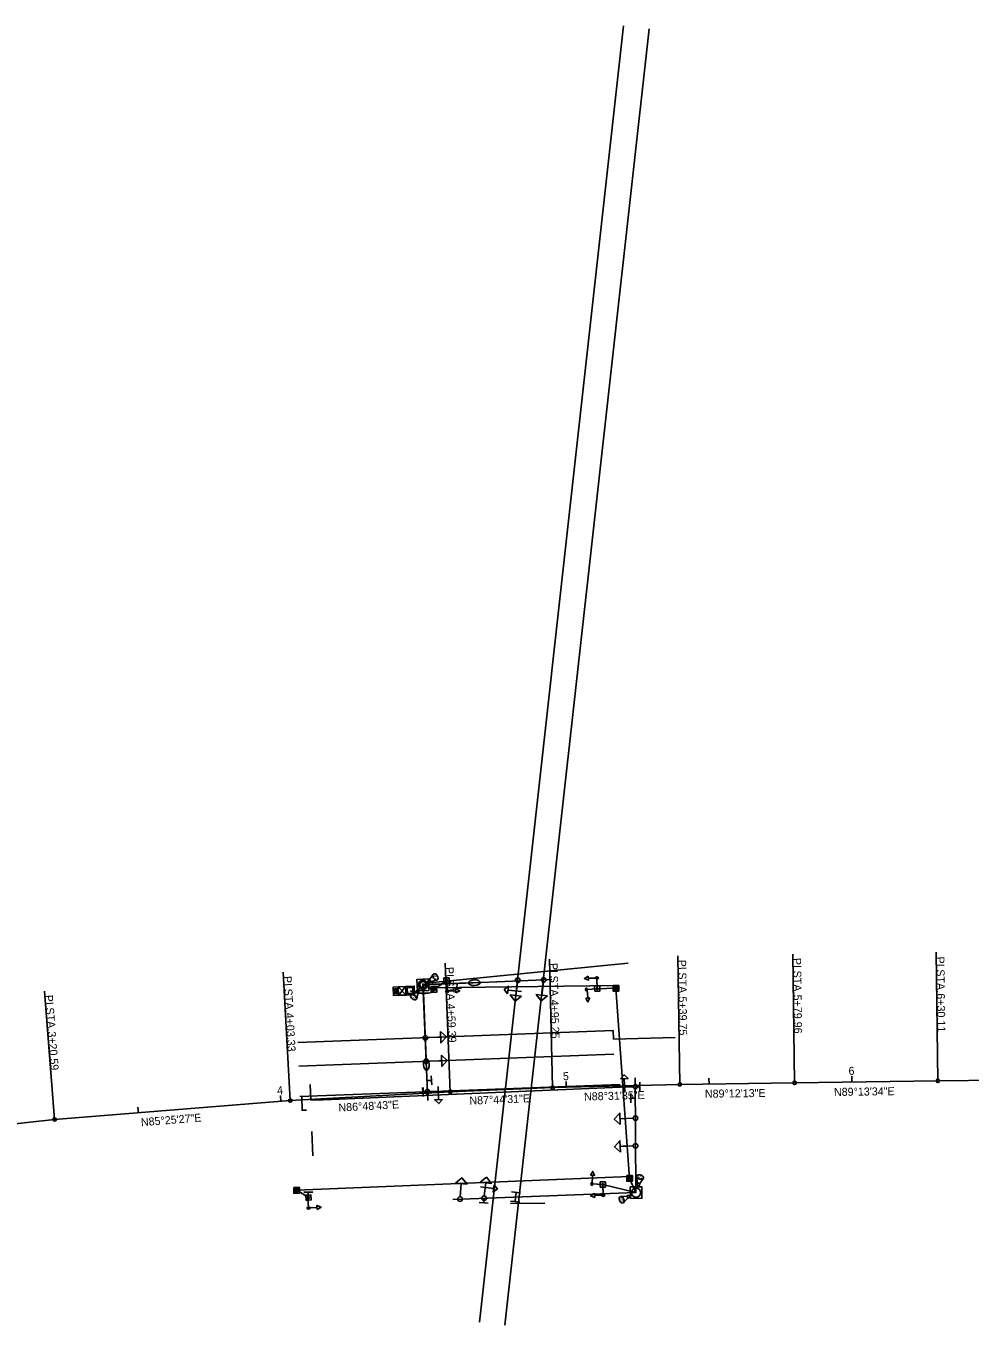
# Model space of a CAD drawing. Extents: x 1369241 to 1370511, y 405823 to 406278.
# Drawn here: x 1369555.1 to 1369885.4, y 405822.9 to 406277.6 of the extents above; entities that cross this region are included whole.
import ezdxf

# ---------------------------------------------------------------- set-up
doc = ezdxf.new("R2010")
doc.units = 0
for name, color, linetype in [('_CIVIL_CONSTRUCTION', 7, 'Continuous'), ('CM_Corridor_Conceptual', 7, 'Continuous'), ('CM_Corridor_Range_Conceptual', 7, 'Continuous'), ('DT_P_Tie', 7, 'Continuous'), ('GE_P_Alignment', 7, 'Continuous'), ('MD_P_ACB_B', 7, 'Continuous'), ('MD_P_ACIC_B', 7, 'Continuous'), ('MD_P_ACSC_T', 7, 'Continuous'), ('MD_P_CSS_B', 7, 'Continuous'), ('MD_P_CURB_BACK_BOT', 7, 'Continuous'), ('MD_P_CURB_BACK_TOP', 7, 'Continuous'), ('MD_P_CURB_FACE_TOP', 7, 'Continuous'), ('PM_P_Crosswalk', 7, 'Continuous'), ('SC_Scratch1', 7, 'Continuous')]:
    doc.layers.add(name, color=color, linetype=linetype)

msp = doc.modelspace()

# ---------------------------------------------------------------- linework, layer by layer
at = {"layer": '_CIVIL_CONSTRUCTION'}
for p, q in [((1369685.39, 405938.97), (1369684.07, 405940.53)), ((1369684.14, 405938.91), (1369685.31, 405940.59)), ((1369688.08, 405938.41), (1369685.28, 405941.28)), ((1369685.42, 405938.28), (1369687.94, 405941.4))]:
    msp.add_line(p, q, dxfattribs=at)
for points in [[(1369691.08, 405938.55), (1369690.94, 405941.54), (1369683.57, 405941.2), (1369683.71, 405938.2)], [(1369685.39, 405938.97), (1369684.14, 405938.91), (1369684.07, 405940.53), (1369685.31, 405940.59)], [(1369688.08, 405938.41), (1369685.42, 405938.28), (1369685.28, 405941.28), (1369687.94, 405941.4)], [(1369691.08, 405938.55), (1369690.94, 405941.54), (1369687.94, 405941.4), (1369688.08, 405938.41)], [(1369690.56, 405939.02), (1369690.46, 405941.02), (1369688.47, 405940.93), (1369688.56, 405938.93)]]:
    msp.add_lwpolyline(points, close=True, dxfattribs=at)
at = {"layer": 'CM_Corridor_Conceptual'}
for p, q in [((1369702.28, 405944.43), (1369702.28, 405944.43)), ((1369728.43, 405939.62), (1369723.76, 405940.16)), ((1369727.07, 405942.78), (1369726.53, 405938.22)), ((1369736.14, 405942.93), (1369735.61, 405938.37)), ((1369756.1, 405940.72), (1369756.1, 405940.72)), ((1369755.03, 405939.65), (1369755.03, 405939.65)), ((1369695.61, 405923.5), (1369700.21, 405923.67)), ((1369695.93, 405915.24), (1369700.52, 405915.41)), ((1369764.6, 405904.48), (1369764.42, 405909.18)), ((1369696.37, 405904.61), (1369700.97, 405904.8)), ((1369699.28, 405906.45), (1369699.48, 405901.75)), ((1369767.52, 405906.31), (1369762.92, 405906.13)), ((1369767.56, 405895.29), (1369762.97, 405895.1)), ((1369767.6, 405885.59), (1369763.01, 405885.4)), ((1369707.05, 405867.81), (1369707.41, 405872.39)), ((1369715.47, 405868.11), (1369715.98, 405872.68)), ((1369756.91, 405873.05), (1369756.91, 405873.05)), ((1369757.88, 405872.04), (1369757.88, 405872.04)), ((1369653.67, 405868.6), (1369653.67, 405868.6)), ((1369714.1, 405871.26), (1369718.77, 405870.74))]:
    msp.add_line(p, q, dxfattribs=at)
for points in [[(1369751.87, 405944.96), (1369751.91, 405943.56), (1369750.49, 405944.22)], [(1369705.49, 405939.15), (1369705.43, 405940.54), (1369706.86, 405939.9)], [(1369723.61, 405938.86), (1369722.44, 405940.34), (1369723.92, 405941.51)], [(1369728.53, 405937.99), (1369726.31, 405936.24), (1369724.55, 405938.46)], [(1369737.59, 405938.14), (1369735.37, 405936.38), (1369733.62, 405938.6)], [(1369750.94, 405937.32), (1369752.34, 405937.43), (1369751.74, 405935.98)], [(1369700.13, 405925.67), (1369702.21, 405923.75), (1369700.28, 405921.67)], [(1369700.45, 405917.41), (1369702.52, 405915.49), (1369700.6, 405913.41)], [(1369763.1, 405909.12), (1369764.38, 405910.5), (1369765.76, 405909.22)], [(1369700.8, 405901.81), (1369699.53, 405900.43), (1369698.14, 405901.7)], [(1369763.05, 405893.1), (1369760.97, 405895.02), (1369762.89, 405897.1)], [(1369763.1, 405883.41), (1369761.01, 405885.32), (1369762.93, 405887.4)], [(1369752.66, 405875.34), (1369754.06, 405875.26), (1369753.44, 405876.7)], [(1369705.42, 405872.55), (1369707.57, 405874.38), (1369709.41, 405872.23)], [(1369713.99, 405872.89), (1369716.2, 405874.66), (1369717.96, 405872.44)], [(1369718.91, 405872.04), (1369720.08, 405870.57), (1369718.61, 405869.39)], [(1369754.1, 405867.54), (1369754.05, 405868.94), (1369752.68, 405868.19)], [(1369656.97, 405863.38), (1369656.89, 405864.78), (1369658.33, 405864.16)]]:
    msp.add_lwpolyline(points, close=True, dxfattribs=at)
for points in [[(1369754.99, 405940.85), (1369754.89, 405944.35), (1369751.89, 405944.26)], [(1369702.33, 405943.23), (1369702.46, 405939.73), (1369705.46, 405939.85)], [(1369754.9, 405940.63), (1369751.41, 405940.37), (1369751.64, 405937.38)], [(1369756.68, 405872.1), (1369753.19, 405872.31), (1369753.36, 405875.3)], [(1369756.95, 405871.85), (1369757.08, 405868.35), (1369754.08, 405868.24)], [(1369653.74, 405867.4), (1369653.94, 405863.91), (1369656.93, 405864.08)]]:
    msp.add_lwpolyline(points, dxfattribs=at)
for centre in [(1369727.16, 405943.58), (1369736.23, 405943.73), (1369694.81, 405923.47), (1369695.13, 405915.21), (1369695.57, 405904.58), (1369768.32, 405906.34), (1369768.36, 405895.33), (1369768.4, 405885.63), (1369706.99, 405867.01), (1369715.38, 405867.31)]:
    msp.add_circle(centre, 0.8, dxfattribs=at)
at = {"layer": 'CM_Corridor_Range_Conceptual'}
for p, q in [((1369694.1, 405939.15), (1369694.05, 405940.75)), ((1369707.49, 405940.72), (1369704.3, 405940.98)), ((1369705.89, 405940.85), (1369706.02, 405942.44)), ((1369705.89, 405940.85), (1369705.89, 405940.85)), ((1369695.7, 405939.2), (1369692.5, 405939.1)), ((1369694.1, 405939.15), (1369694.1, 405939.15)), ((1369696.98, 405908.53), (1369695.38, 405908.46)), ((1369696.92, 405910.13), (1369697.05, 405906.93)), ((1369696.98, 405908.53), (1369696.98, 405908.53)), ((1369694.06, 405902.86), (1369693.81, 405906.05)), ((1369693.94, 405904.45), (1369695.53, 405904.58)), ((1369693.94, 405904.45), (1369693.94, 405904.45)), ((1369766.74, 405900.73), (1369766.73, 405903.93)), ((1369769.92, 405906.34), (1369768.32, 405906.34)), ((1369769.91, 405907.94), (1369769.92, 405904.74)), ((1369769.92, 405906.34), (1369769.92, 405906.34)), ((1369766.73, 405902.33), (1369768.33, 405902.34)), ((1369766.73, 405902.33), (1369766.73, 405902.33)), ((1369652.26, 405869.4), (1369655.46, 405869.47)), ((1369653.86, 405869.44), (1369653.9, 405867.84)), ((1369653.86, 405869.44), (1369653.86, 405869.44)), ((1369715.25, 405865.73), (1369715.38, 405867.32)), ((1369724.98, 405869.48), (1369728.16, 405869.13)), ((1369726.26, 405866.13), (1369726.39, 405867.72)), ((1369726.57, 405869.3), (1369726.39, 405867.71)), ((1369726.57, 405869.3), (1369726.57, 405869.3)), ((1369716.84, 405865.6), (1369713.65, 405865.86)), ((1369715.25, 405865.73), (1369715.25, 405865.73)), ((1369727.86, 405866), (1369724.67, 405866.26)), ((1369726.26, 405866.13), (1369726.26, 405866.13))]:
    msp.add_line(p, q, dxfattribs=at)
at = {"layer": 'DT_P_Tie'}
for p, q in [((1369696.3, 405943.8), (1369697.54, 405945.64)), ((1369697.54, 405945.64), (1369696.3, 405943.8)), ((1369693.03, 405941), (1369692.43, 405940.13)), ((1369695.02, 405942.47), (1369695.89, 405943.07)), ((1369696.3, 405943.8), (1369696.72, 405943.18)), ((1369696.72, 405943.18), (1369698.89, 405943.65)), ((1369696.72, 405943.18), (1369698.89, 405943.65)), ((1369703.02, 405939.87), (1369701.9, 405939.82)), ((1369702.32, 405943.44), (1369702.46, 405939.85)), ((1369751.45, 405939.81), (1369751.37, 405940.93)), ((1369755, 405940.64), (1369751.41, 405940.37)), ((1369754.33, 405944.22), (1369755.45, 405944.25)), ((1369755, 405940.64), (1369754.89, 405944.24)), ((1369691.7, 405939.72), (1369689.85, 405938.5)), ((1369691.7, 405939.72), (1369689.85, 405938.5)), ((1369692.32, 405939.3), (1369691.7, 405939.72)), ((1369692.32, 405939.3), (1369691.83, 405937.14)), ((1369691.83, 405937.14), (1369692.32, 405939.3)), ((1369753.38, 405872.86), (1369753.32, 405871.74)), ((1369756.94, 405872.09), (1369753.35, 405872.3)), ((1369756.94, 405872.09), (1369757.07, 405868.49)), ((1369769.13, 405872.63), (1369768.78, 405874.82)), ((1369768.78, 405874.82), (1369769.13, 405872.63)), ((1369769.09, 405870.78), (1369769.33, 405871.81)), ((1369769.13, 405872.63), (1369769.86, 405872.46)), ((1369769.86, 405872.46), (1369771.12, 405874.28)), ((1369769.86, 405872.46), (1369771.12, 405874.28)), ((1369653.72, 405867.66), (1369653.93, 405864.06)), ((1369756.51, 405868.47), (1369757.63, 405868.51)), ((1369765.39, 405868.05), (1369763.18, 405867.95)), ((1369765.39, 405868.05), (1369763.18, 405867.95)), ((1369765.71, 405867.37), (1369764.18, 405865.77)), ((1369764.18, 405865.77), (1369765.71, 405867.37)), ((1369765.71, 405867.37), (1369765.39, 405868.05)), ((1369767.2, 405868.46), (1369766.23, 405868.02)), ((1369654.49, 405864.1), (1369653.37, 405864.03))]:
    msp.add_line(p, q, dxfattribs=at)
for points in [[(1369692.74, 405939.92), (1369692.12, 405940.34), (1369691.7, 405939.72), (1369692.32, 405939.3)], [(1369695.68, 405943.38), (1369696.1, 405942.76), (1369696.72, 405943.18), (1369696.3, 405943.8)], [(1369768.96, 405871.9), (1369769.69, 405871.73), (1369769.86, 405872.46), (1369769.13, 405872.63)], [(1369766.39, 405867.68), (1369766.08, 405868.37), (1369765.39, 405868.05), (1369765.71, 405867.37)]]:
    msp.add_lwpolyline(points, close=True, dxfattribs=at)
for points in [[(1369692.74, 405939.92), (1369692.12, 405940.34), (1369691.7, 405939.72), (1369692.32, 405939.3), (1369692.74, 405939.92)], [(1369695.68, 405943.38), (1369696.1, 405942.76), (1369696.72, 405943.18), (1369696.3, 405943.8), (1369695.68, 405943.38)], [(1369768.96, 405871.9), (1369769.69, 405871.73), (1369769.86, 405872.46), (1369769.13, 405872.63), (1369768.96, 405871.9)], [(1369766.39, 405867.68), (1369766.08, 405868.37), (1369765.39, 405868.05), (1369765.71, 405867.37), (1369766.39, 405867.68)]]:
    msp.add_lwpolyline(points, dxfattribs=at)
for centre, start, end in [((1369754.89, 405944.24), 1.7331, 181.7327), ((1369702.46, 405939.85), 182.1814, 2.181), ((1369751.41, 405940.37), 94.3061, 274.3057), ((1369753.35, 405872.3), 86.695, 266.6946), ((1369757.07, 405868.49), 182.0638, 2.0634), ((1369653.93, 405864.06), 183.273, 3.2727)]:
    msp.add_arc(centre, 0.56, start, end, dxfattribs=at)
for centre, major_axis in [((1369698.37, 405944.75), (0.7, -1.02)), ((1369690.73, 405937.66), (-1.02, 0.7)), ((1369769.99, 405874.73), (1.21, -0.28)), ((1369763.51, 405866.78), (-0.51, 1.13))]:
    msp.add_ellipse(centre, major_axis=major_axis, ratio=0.621318, dxfattribs=at)
for centre, major_axis in [((1369698.37, 405944.75), (0.7, -1.02)), ((1369690.73, 405937.66), (-1.02, 0.7)), ((1369769.99, 405874.73), (1.21, -0.28)), ((1369763.51, 405866.78), (-0.51, 1.13))]:
    msp.add_ellipse(centre, major_axis=major_axis, ratio=0.621318, start_param=3.386213, end_param=6.038231, dxfattribs=at)
at = {"layer": 'GE_P_Alignment'}
for points in [[(1369701.41, 405942.6), (1369703.21, 405942.65), (1369703.15, 405944.45), (1369701.35, 405944.4)], [(1369692.09, 405939.85), (1369696.09, 405940.05), (1369695.89, 405944.04), (1369691.9, 405943.85)], [(1369754.13, 405939.71), (1369755.93, 405939.79), (1369755.85, 405941.59), (1369754.05, 405941.5)], [(1369756.04, 405871.19), (1369757.84, 405871.19), (1369757.84, 405872.99), (1369756.04, 405872.99)], [(1369653.12, 405866.56), (1369654.91, 405866.73), (1369654.74, 405868.52), (1369652.95, 405868.35)], [(1369766.62, 405867.23), (1369770.62, 405867.3), (1369770.55, 405871.29), (1369766.55, 405871.23)]]:
    msp.add_lwpolyline(points, close=True, dxfattribs=at)
for centre, radius in [((1369702.28, 405943.52), 0.3), ((1369754.99, 405940.65), 0.3), ((1369756.94, 405872.09), 0.3), ((1369653.93, 405867.54), 0.3), ((1369768.59, 405869.26), 1.6)]:
    msp.add_circle(centre, radius, dxfattribs=at)
msp.add_ellipse((1369693.99, 405941.95), major_axis=(1.6, 0.08), ratio=0.999752, dxfattribs=at)
at = {"layer": 'MD_P_ACB_B'}
for p, q in [((1369697.81, 405940.4), (1369697.81, 405940.4)), ((1369761.51, 405940.79), (1369761.51, 405940.79)), ((1369766.29, 405874.24), (1369766.29, 405874.24)), ((1369649.75, 405870.07), (1369649.75, 405870.07))]:
    msp.add_line(p, q, dxfattribs=at)
for points in [[(1369696.76, 405941.34), (1369698.75, 405941.46), (1369698.87, 405939.46), (1369696.87, 405939.34)], [(1369760.51, 405941.79), (1369762.51, 405941.79), (1369762.51, 405939.79), (1369760.51, 405939.79)], [(1369765.29, 405875.24), (1369767.29, 405875.24), (1369767.29, 405873.24), (1369765.29, 405873.24)], [(1369648.75, 405871.07), (1369650.75, 405871.07), (1369650.75, 405869.07), (1369648.75, 405869.07)]]:
    msp.add_lwpolyline(points, close=True, dxfattribs=at)
for points in [[(1369696.87, 405941.01), (1369697.7, 405941.06)], [(1369697.29, 405941.03), (1369697.37, 405939.7)], [(1369697.93, 405939.74), (1369697.85, 405941.07), (1369698.35, 405941.1), (1369698.4, 405941.09), (1369698.48, 405941.07), (1369698.51, 405941.05), (1369698.54, 405941.04), (1369698.59, 405940.99), (1369698.62, 405940.94), (1369698.65, 405940.85), (1369698.66, 405940.73), (1369698.65, 405940.68), (1369698.63, 405940.62), (1369698.59, 405940.54), (1369698.55, 405940.51), (1369698.52, 405940.49), (1369698.5, 405940.48), (1369698.47, 405940.46), (1369698.38, 405940.45), (1369697.89, 405940.42)], [(1369698.38, 405940.45), (1369698.71, 405939.78)], [(1369760.6, 405941.45), (1369761.43, 405941.45)], [(1369761.02, 405941.45), (1369761.02, 405940.12)], [(1369761.58, 405940.12), (1369761.58, 405941.45), (1369762.09, 405941.45), (1369762.14, 405941.44), (1369762.21, 405941.42), (1369762.24, 405941.4), (1369762.28, 405941.38), (1369762.32, 405941.33), (1369762.35, 405941.27), (1369762.37, 405941.19), (1369762.37, 405941.06), (1369762.36, 405941.02), (1369762.34, 405940.96), (1369762.3, 405940.89), (1369762.25, 405940.85), (1369762.22, 405940.83), (1369762.2, 405940.82), (1369762.17, 405940.81), (1369762.08, 405940.8), (1369761.58, 405940.8)], [(1369762.08, 405940.8), (1369762.37, 405940.12)], [(1369765.38, 405874.9), (1369766.21, 405874.9)], [(1369765.8, 405874.9), (1369765.8, 405873.57)], [(1369766.36, 405873.57), (1369766.36, 405874.9), (1369766.87, 405874.9), (1369766.92, 405874.89), (1369766.99, 405874.87), (1369767.02, 405874.85), (1369767.05, 405874.83), (1369767.1, 405874.78), (1369767.13, 405874.72), (1369767.15, 405874.64), (1369767.15, 405874.51), (1369767.14, 405874.47), (1369767.12, 405874.41), (1369767.08, 405874.34), (1369767.03, 405874.3), (1369767, 405874.28), (1369766.98, 405874.27), (1369766.95, 405874.26), (1369766.85, 405874.25), (1369766.36, 405874.25)], [(1369766.85, 405874.25), (1369767.15, 405873.57)], [(1369648.85, 405870.74), (1369649.68, 405870.74)], [(1369649.27, 405870.74), (1369649.27, 405869.41)], [(1369649.83, 405869.41), (1369649.83, 405870.74), (1369650.33, 405870.74), (1369650.39, 405870.73), (1369650.46, 405870.71), (1369650.49, 405870.69), (1369650.52, 405870.67), (1369650.56, 405870.61), (1369650.6, 405870.56), (1369650.62, 405870.48), (1369650.62, 405870.35), (1369650.61, 405870.31), (1369650.59, 405870.25), (1369650.54, 405870.17), (1369650.5, 405870.14), (1369650.47, 405870.12), (1369650.45, 405870.11), (1369650.42, 405870.1), (1369650.32, 405870.09), (1369649.83, 405870.09)], [(1369650.32, 405870.09), (1369650.62, 405869.41)]]:
    msp.add_lwpolyline(points, dxfattribs=at)
at = {"layer": 'MD_P_ACIC_B'}
for p, q in [((1369693.99, 405942.47), (1369695.7, 405901.5)), ((1369697.81, 405940.4), (1369694.03, 405942.06)), ((1369761.54, 405941.71), (1369697.68, 405940.95)), ((1369702.32, 405943.48), (1369697.81, 405940.4)), ((1369761.51, 405940.79), (1369755, 405940.64)), ((1369761.51, 405940.79), (1369766.29, 405874.24)), ((1369766.24, 405874.9), (1369649.83, 405870.08)), ((1369768.52, 405869.25), (1369756.94, 405872.09)), ((1369766.29, 405874.24), (1369768.52, 405869.25)), ((1369649.83, 405870.08), (1369653.93, 405867.54))]:
    msp.add_line(p, q, dxfattribs=at)
msp.add_arc((1369693.98, 405949.72), 10.77, 245.4119, 291.0837, dxfattribs=at)
at = {"layer": 'MD_P_ACSC_T'}
for p, q in [((1369694.01, 405942.06), (1369709.99, 405942.66)), ((1369694.01, 405942.07), (1369695.09, 405916.09))]:
    msp.add_line(p, q, dxfattribs=at)
for centre in [(1369694.01, 405942.07), (1369694.01, 405942.06)]:
    msp.add_circle(centre, 1.1, dxfattribs=at)
for centre, major_axis in [((1369711.99, 405942.73), (2, 0.08)), ((1369695.17, 405914.09), (0.08, -2))]:
    msp.add_ellipse(centre, major_axis=major_axis, ratio=0.5, dxfattribs=at)
at = {"layer": 'MD_P_CSS_B'}
for p, q in [((1369744.13, 405906.12), (1369744.08, 405908.12)), ((1369794.12, 405907.28), (1369794.09, 405909.28)), ((1369824.07, 405907.7), (1369874.22, 405908.38)), ((1369844.11, 405907.97), (1369844.09, 405909.97)), ((1369874.22, 405908.38), (1369958.19, 405909.51)), ((1369647.58, 405901.47), (1369703.55, 405904.59)), ((1369694.18, 405904.06), (1369694.06, 405906.06)), ((1369703.55, 405904.59), (1369739.38, 405906)), ((1369739.38, 405906), (1369783.87, 405907.14)), ((1369783.87, 405907.14), (1369824.07, 405907.7)), ((1369565.1, 405894.87), (1369647.58, 405901.47)), ((1369594.42, 405897.21), (1369594.26, 405899.21)), ((1369644.26, 405901.2), (1369644.1, 405903.2)), ((1369493.58, 405887.19), (1369565.1, 405894.87))]:
    msp.add_line(p, q, dxfattribs=at)
at = {"layer": 'MD_P_CURB_BACK_BOT'}
for p, q in [((1369713.74, 405823.92), (1369764.23, 406277.56)), ((1369722.69, 405822.93), (1369773.18, 406276.56)), ((1369760.57, 405925.96), (1369650.23, 405921.77)), ((1369760.66, 405922.96), (1369760.57, 405925.96)), ((1369782.24, 405923.55), (1369760.66, 405922.94)), ((1369760.81, 405917.7), (1369650.54, 405913.51)), ((1369762.99, 405907.16), (1369650.95, 405902.9)), ((1369656.47, 405901.66), (1369765.79, 405906.23)), ((1369763.96, 405885.47), (1369765.07, 405885.47)), ((1369655.32, 405885.08), (1369655.41, 405882.08)), ((1369736.59, 405865.56), (1369724.59, 405865.44))]:
    msp.add_line(p, q, dxfattribs=at)
at = {"layer": 'MD_P_CURB_BACK_TOP'}
for p, q in [((1369651.58, 405902.91), (1369651.77, 405897.91)), ((1369651.81, 405898.11), (1369653.23, 405898.17))]:
    msp.add_line(p, q, dxfattribs=at)
at = {"layer": 'MD_P_CURB_FACE_TOP'}
msp.add_line((1369765.82, 405949.51), (1369695.07, 405942.51), dxfattribs=at)
at = {"layer": 'PM_P_Crosswalk'}
for p, q in [((1369703.55, 405904.59), (1369701.78, 405949.55)), ((1369739.38, 405906), (1369738.23, 405950.98)), ((1369783.87, 405907.14), (1369783.24, 405952.14)), ((1369824.07, 405907.7), (1369823.47, 405952.7)), ((1369874.22, 405908.38), (1369873.61, 405953.37)), ((1369647.58, 405901.47), (1369645.08, 405946.4)), ((1369694.01, 405942.06), (1369713.99, 405942.83)), ((1369565.1, 405894.87), (1369561.51, 405939.72)), ((1369654.55, 405907.07), (1369654.74, 405901.6)), ((1369654.74, 405901.6), (1369658.11, 405901.71)), ((1369655.32, 405885.08), (1369655.12, 405890.6))]:
    msp.add_line(p, q, dxfattribs=at)
for centre in [(1369824.07, 405907.7), (1369874.22, 405908.38), (1369703.55, 405904.59), (1369739.38, 405906), (1369783.87, 405907.14), (1369647.58, 405901.47), (1369565.1, 405894.87)]:
    msp.add_circle(centre, 0.6, dxfattribs=at)
at = {"layer": 'SC_Scratch1'}
for p, q in [((1369739.13, 405943.88), (1369695.07, 405941.99)), ((1369768.52, 405869.16), (1369768.3, 405909.38)), ((1369704.5, 405866.91), (1369768.52, 405869.25))]:
    msp.add_line(p, q, dxfattribs=at)

# ---------------------------------------------------------------- texts
at = {"layer": 'DT_P_Tie'}
for rotation, p in [(34.2934, (1369698.31, 405943.86)), (235.4894, (1369690.47, 405938.51)), (77.2013, (1369770.55, 405874.04)), (204.5251, (1369763.72, 405867.65))]:
    msp.add_text('S', height=1.4, rotation=rotation, dxfattribs=at).set_placement(p)
at = {"layer": 'MD_P_CSS_B'}
for s, rotation, p in [('6', 0.7739, (1369842.96, 405910.46)), ('5', 1.4737, (1369743, 405908.59)), ('4', 4.5757, (1369643.03, 405903.61))]:
    msp.add_text(s, height=2.8, rotation=rotation, dxfattribs=at).set_placement(p)
at = {"layer": 'PM_P_Crosswalk'}
for s, rotation, p in [('PI', 271.4737, (1369738.31, 405949.6)), ('PI', 270.7963, (1369783.3, 405950.76)), ('PI', 270.7739, (1369823.53, 405951.37)), ('PI', 270.7739, (1369873.67, 405951.84)), ('PI', 273.1881, (1369645.2, 405944.99)), ('PI', 272.258, (1369701.88, 405948.18)), (' STA. ', 271.4737, (1369738.39, 405946.21)), (' STA. ', 270.7963, (1369783.35, 405947.36)), (' STA. ', 270.7739, (1369823.57, 405947.98)), (' STA. ', 270.7739, (1369873.72, 405948.45)), (' STA. ', 273.1881, (1369645.39, 405941.6)), (' STA. ', 272.258, (1369702.01, 405944.8)), ('PI', 274.5757, (1369561.66, 405938.36)), ('4+59.39', 272.258, (1369702.38, 405935.35)), ('4+95.25', 271.4737, (1369738.64, 405936.76)), ('5+39.75', 270.7963, (1369783.48, 405937.91)), ('5+79.96', 270.7739, (1369823.7, 405938.53)), ('6+30.11', 270.7739, (1369873.85, 405939)), (' STA. ', 274.5757, (1369561.93, 405934.98)), ('4+03.33', 273.1881, (1369645.91, 405932.16)), ('3+20.59', 274.5757, (1369562.69, 405925.56)), ('N87°44\'31"E', 2.258, (1369710.3, 405900.05)), ('N88°31\'35"E', 1.4737, (1369750.39, 405901.48)), ('N89°12\'13"E', 0.7963, (1369792.68, 405902.46)), ('N89°13\'34"E', 0.7739, (1369837.85, 405903.09)), ('N86°48\'43"E', 3.1881, (1369664.49, 405897.6)), ('N85°25\'27"E', 4.5757, (1369595.4, 405892.48))]:
    msp.add_text(s, height=2.8, rotation=rotation, dxfattribs=at).set_placement(p)

doc.saveas('drawing.dxf')
